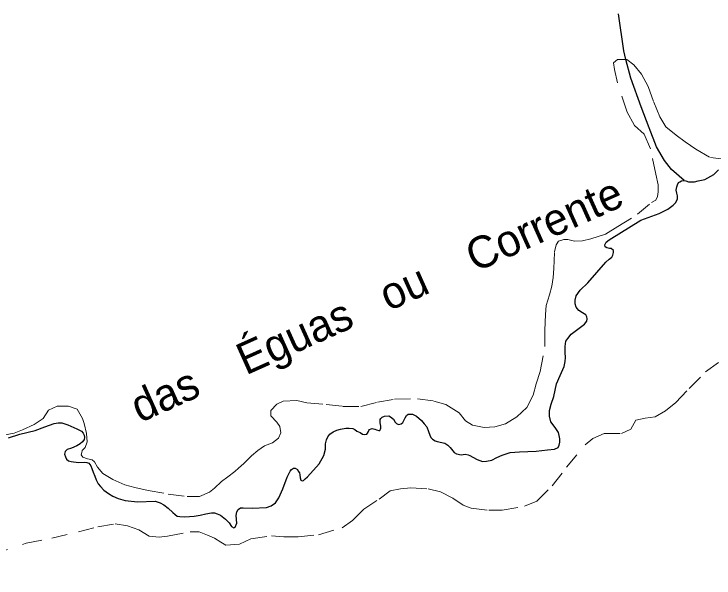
# Model space of a CAD drawing. Extents: x 391.8 to 446, y 8452 to 8507.5.
# Drawn here: x 426.92 to 431.31, y 8502.725 to 8506.265 of the extents above; entities that cross this region are included whole.
import ezdxf
from ezdxf.enums import TextEntityAlignment as Align

# ---------------------------------------------------------------- set-up
doc = ezdxf.new("R2010")
doc.units = 0
doc.header["$LTSCALE"] = 0.064
doc.linetypes.add('SHORT_DASHED', pattern=[2.7, 1.5, -1.2])
doc.layers.add('21', color=7, linetype='SHORT_DASHED', lineweight=13)
doc.layers.add('7', color=7, linetype='Continuous', lineweight=25)
doc.layers.add('61', color=7, linetype='Continuous')

msp = doc.modelspace()

# ---------------------------------------------------------------- linework, layer by layer
at = {"layer": '21'}
for points in [[(430.812, 8505.5655), (430.764, 8505.654), (430.7045, 8505.8321), (430.6861, 8505.9169), (430.6787, 8505.9575), (430.7045, 8505.9796), (430.758, 8505.9796)], [(430.758, 8505.9796), (430.7636, 8505.9796), (430.8079, 8505.9464), (430.8559, 8505.8874), (430.8965, 8505.81), (430.9334, 8505.7104), (430.9704, 8505.6183), (431.0073, 8505.5556), (431.0737, 8505.504), (431.1291, 8505.4634), (431.1956, 8505.4155), (431.2879, 8505.3638), (431.3728, 8505.3528)], [(430.956, 8505.1194), (430.9597, 8505.1489), (430.9597, 8505.1931), (430.9449, 8505.2595), (430.9117, 8505.418), (430.8711, 8505.5102), (430.812, 8505.5655)], [(426.8442, 8503.6189), (426.9217, 8503.6337), (426.9734, 8503.6558), (427.0472, 8503.689), (427.1026, 8503.7259), (427.1359, 8503.7775), (427.1912, 8503.8033), (427.2614, 8503.8033), (427.3168, 8503.7849), (427.35, 8503.7259), (427.3592, 8503.6942), (427.374, 8503.6315), (427.3777, 8503.5799), (427.3666, 8503.543), (427.3481, 8503.5246), (427.3445, 8503.5135), (427.3408, 8503.4988), (427.3518, 8503.484), (427.3814, 8503.473), (427.4109, 8503.4656), (427.4257, 8503.4545), (427.4441, 8503.4213), (427.4774, 8503.3808), (427.5401, 8503.3439), (427.614, 8503.3107), (427.6767, 8503.2923), (427.7616, 8503.2739), (427.8872, 8503.2517), (428.0053, 8503.237), (428.0828, 8503.237), (428.1456, 8503.2628), (428.1766, 8503.2896), (428.2209, 8503.3301), (428.2615, 8503.3596), (428.3058, 8503.3928), (428.328, 8503.4149), (428.3612, 8503.4444), (428.4092, 8503.4923), (428.4498, 8503.5255), (428.4904, 8503.555), (428.5421, 8503.5735), (428.579, 8503.603), (428.5938, 8503.6361), (428.5864, 8503.6767), (428.568, 8503.7025), (428.531, 8503.7431), (428.531, 8503.7763), (428.568, 8503.8168), (428.6086, 8503.8352), (428.6935, 8503.8389), (428.7562, 8503.8242), (428.8781, 8503.8131), (428.9815, 8503.8021), (429.0959, 8503.8021), (429.1993, 8503.8279), (429.3063, 8503.8463), (429.4503, 8503.85), (429.5537, 8503.8352), (429.6275, 8503.8131), (429.7125, 8503.7615), (429.7513, 8503.7104), (429.7956, 8503.6846), (429.8695, 8503.6698), (429.9359, 8503.6735), (430.0024, 8503.6919), (430.0725, 8503.7362), (430.1353, 8503.7952), (430.1759, 8503.8726), (430.1944, 8503.9427), (430.2202, 8504.0201), (430.2498, 8504.1786), (430.2493, 8504.2799), (430.253, 8504.3795), (430.2567, 8504.4348), (430.2788, 8504.5011), (430.2936, 8504.5564), (430.301, 8504.6117), (430.3047, 8504.667), (430.309, 8504.7716), (430.32, 8504.8158), (430.3348, 8504.838), (430.368, 8504.849), (430.3939, 8504.849), (430.4345, 8504.838), (430.4862, 8504.8416), (430.5379, 8504.8527), (430.6302, 8504.8822), (430.7077, 8504.9301), (430.8295, 8505.0076), (430.9181, 8505.0813), (430.9449, 8505.0972), (430.956, 8505.1194)], [(427.5547, 8503.0651), (427.6318, 8503.0523), (427.7025, 8503.0266), (427.7668, 8502.9881), (427.8311, 8502.9817), (427.8825, 8502.9881), (428.0239, 8503.0138), (428.0818, 8503.0138), (428.1332, 8502.9945), (428.1782, 8502.9753), (428.2168, 8502.9496), (428.2489, 8502.9303), (428.3351, 8502.9381), (428.4058, 8502.9702), (428.5343, 8502.9894), (428.6115, 8502.983), (428.7015, 8502.983), (428.83, 8502.9958), (428.9779, 8503.0408), (429.0422, 8503.0857), (429.1129, 8503.1563), (429.2093, 8503.2205), (429.28, 8503.2719), (429.3443, 8503.2847), (429.4086, 8503.2912), (429.5179, 8503.2847), (429.595, 8503.2655), (429.6722, 8503.227), (429.7364, 8503.182), (429.7879, 8503.1628), (429.8972, 8503.1499), (429.9807, 8503.1499), (430.1221, 8503.1756), (430.1993, 8503.2077), (430.2957, 8503.304), (430.3857, 8503.4196), (430.5014, 8503.5608), (430.5499, 8503.6007), (430.6206, 8503.6328), (430.7299, 8503.6328), (430.7877, 8503.6585), (430.8199, 8503.7163), (430.8777, 8503.7291), (430.942, 8503.7355), (431.0063, 8503.774), (431.0706, 8503.8254), (431.1541, 8503.9153), (431.257, 8504.018), (431.3811, 8504.1102)], [(426.4811, 8502.7249), (426.7833, 8502.8725), (426.9954, 8502.9432), (427.1561, 8502.9753), (427.3233, 8503.0138), (427.4454, 8503.0459), (427.5547, 8503.0651)]]:
    msp.add_lwpolyline(points, dxfattribs=at)
at = {"layer": '7'}
for points in [[(430.758, 8505.9796), (430.7446, 8506.0333), (430.7115, 8506.2647)], [(431.1232, 8505.219), (431.0426, 8505.2893), (430.9995, 8505.3455), (430.9499, 8505.4315), (430.9035, 8505.5505), (430.8538, 8505.6828), (430.7876, 8505.8613), (430.758, 8505.9796)], [(431.1232, 8505.219), (431.1332, 8505.217), (431.1499, 8505.2123), (431.1879, 8505.2123), (431.2117, 8505.217), (431.2521, 8505.2265), (431.3092, 8505.2574), (431.3384, 8505.2875)], [(430.5061, 8504.377), (430.4848, 8504.3897), (430.4613, 8504.4047), (430.4464, 8504.4238), (430.44, 8504.4451), (430.44, 8504.4686), (430.4464, 8504.4963), (430.4699, 8504.5304), (430.5189, 8504.5772), (430.632, 8504.7072), (430.6534, 8504.7252), (430.6683, 8504.738), (430.6747, 8504.7508), (430.679, 8504.7678), (430.679, 8504.7806), (430.6641, 8504.7934), (430.6555, 8504.7934), (430.6385, 8504.7977), (430.6278, 8504.804), (430.6257, 8504.8168), (430.6342, 8504.8317), (430.6534, 8504.8467), (430.8518, 8504.9702), (430.9668, 8505.0128), (431.0215, 8505.0389), (431.0548, 8505.065), (431.069, 8505.0793), (431.0809, 8505.103), (431.0809, 8505.1244), (431.0762, 8505.141), (431.0738, 8505.16), (431.0762, 8505.179), (431.0809, 8505.1933), (431.088, 8505.2075), (431.0952, 8505.2123), (431.1071, 8505.217), (431.1213, 8505.2194), (431.1232, 8505.219)], [(430.3931, 8504.2289), (430.4144, 8504.2544), (430.4976, 8504.3183), (430.5125, 8504.3365), (430.5147, 8504.3514), (430.5125, 8504.3642), (430.5061, 8504.377)], [(428.9448, 8503.6529), (428.9683, 8503.6593), (429.0003, 8503.6657), (429.0216, 8503.6657), (429.0451, 8503.6635), (429.0579, 8503.6571), (429.0707, 8503.6465), (429.0899, 8503.638), (429.1048, 8503.6273), (429.1176, 8503.6252), (429.1326, 8503.6273), (429.1368, 8503.6337), (429.1432, 8503.6443), (429.1454, 8503.6507), (429.1496, 8503.6571), (429.1603, 8503.6614), (429.1667, 8503.6635), (429.1838, 8503.6593), (429.1923, 8503.655), (429.2072, 8503.6507), (429.2136, 8503.6507), (429.2179, 8503.6593), (429.22, 8503.6657), (429.22, 8503.6784), (429.2158, 8503.6997), (429.2158, 8503.7189), (429.22, 8503.7253), (429.2286, 8503.7338), (429.2435, 8503.7402), (429.2712, 8503.7423), (429.2819, 8503.736), (429.2989, 8503.721), (429.3096, 8503.704), (429.3181, 8503.6955), (429.3309, 8503.6891), (429.348, 8503.6933), (429.3587, 8503.7019), (429.3672, 8503.7168), (429.3736, 8503.7296), (429.3821, 8503.7445), (429.3928, 8503.753), (429.4184, 8503.753), (429.444, 8503.7402), (429.476, 8503.7125), (429.4931, 8503.6933), (429.508, 8503.6742), (429.5187, 8503.6443), (429.5272, 8503.6209), (429.5336, 8503.606), (429.5443, 8503.5953), (429.5613, 8503.5868), (429.5741, 8503.5826), (429.6211, 8503.5719), (429.6403, 8503.5591), (429.6552, 8503.5442), (429.6723, 8503.5229), (429.6808, 8503.5123), (429.6957, 8503.5037), (429.7235, 8503.4973), (429.75, 8503.5015), (429.7692, 8503.4972), (429.7777, 8503.493), (429.7969, 8503.4823), (429.8247, 8503.4695), (429.8588, 8503.4568), (429.8823, 8503.4589), (429.9164, 8503.4653), (429.9484, 8503.4802), (429.9825, 8503.4951), (430.0316, 8503.5122), (430.0892, 8503.5164), (430.1937, 8503.5207), (430.2662, 8503.5292), (430.3089, 8503.5335), (430.3324, 8503.5441), (430.3388, 8503.559), (430.343, 8503.5782), (430.343, 8503.5974), (430.3388, 8503.6187), (430.3345, 8503.6378), (430.3132, 8503.6698), (430.2876, 8503.706), (430.279, 8503.7401), (430.279, 8503.7763), (430.2897, 8503.8168), (430.3046, 8503.8637), (430.3227, 8503.9434), (430.3462, 8503.9967), (430.3696, 8504.052), (430.376, 8504.084), (430.3782, 8504.1096), (430.376, 8504.1394), (430.376, 8504.1777), (430.3803, 8504.2118), (430.3931, 8504.2289)], [(426.8853, 8503.6037), (426.9557, 8503.6271), (427.0517, 8503.6506), (427.1135, 8503.674), (427.1711, 8503.6953), (427.1967, 8503.6996), (427.2202, 8503.6996), (427.2565, 8503.6868), (427.3141, 8503.6612), (427.3439, 8503.6463), (427.3546, 8503.6335), (427.3589, 8503.6208), (427.361, 8503.6058), (427.3589, 8503.5952), (427.3503, 8503.5803), (427.3354, 8503.5675), (427.3141, 8503.5547), (427.2799, 8503.5398), (427.2543, 8503.5313), (427.2415, 8503.5185), (427.2373, 8503.5015), (427.2437, 8503.4844), (427.2501, 8503.4716), (427.2607, 8503.461), (427.2778, 8503.4567), (427.3247, 8503.4503), (427.3597, 8503.4518), (427.3768, 8503.4497), (427.3896, 8503.4454), (427.4024, 8503.4284), (427.4088, 8503.4113), (427.4173, 8503.39), (427.4259, 8503.3645), (427.4344, 8503.341), (427.4472, 8503.3155), (427.4621, 8503.2984), (427.4835, 8503.2771), (427.5133, 8503.2558), (427.5389, 8503.2388), (427.5731, 8503.2238), (427.6179, 8503.2111), (427.6946, 8503.2025), (427.8056, 8503.2068), (427.8362, 8503.1971), (427.8597, 8503.1843), (427.8874, 8503.163), (427.9151, 8503.1353), (427.9301, 8503.1225), (427.9429, 8503.114), (427.9599, 8503.1119), (427.9919, 8503.1098), (428.0495, 8503.114), (428.0879, 8503.1183), (428.123, 8503.1272), (428.1593, 8503.1336), (428.1768, 8503.1339), (428.1946, 8503.1268), (428.2159, 8503.1183), (428.2458, 8503.0949), (428.2693, 8503.0714), (428.2836, 8503.0483), (428.2985, 8503.0398), (428.3077, 8503.0437), (428.3171, 8503.0689), (428.3141, 8503.1162), (428.3183, 8503.1405), (428.3251, 8503.1551), (428.3411, 8503.1644), (428.3567, 8503.1652), (428.4143, 8503.163), (428.5039, 8503.1673), (428.5324, 8503.1789), (428.5601, 8503.196), (428.5814, 8503.2279), (428.6049, 8503.2854), (428.6326, 8503.3579), (428.6518, 8503.3962), (428.6604, 8503.4069), (428.6732, 8503.4133), (428.6838, 8503.4133), (428.6988, 8503.4069), (428.703, 8503.3962), (428.7094, 8503.3856), (428.7116, 8503.3728), (428.7137, 8503.3536), (428.718, 8503.3387), (428.7265, 8503.3344), (428.735, 8503.3366), (428.7457, 8503.3472), (428.7606, 8503.36), (428.8332, 8503.441), (428.8638, 8503.4931), (428.8744, 8503.5336)], [(428.8744, 8503.5336), (428.8744, 8503.5676), (428.8787, 8503.5911), (428.8872, 8503.6103), (428.9, 8503.6273), (428.9214, 8503.6422), (428.9448, 8503.6529)]]:
    msp.add_lwpolyline(points, dxfattribs=at)

# ---------------------------------------------------------------- texts
at = {"layer": '61'}
msp.add_text('Rio                        das    Éguas   ou    Corrente', height=0.2, rotation=24.199, dxfattribs=at).set_placement((428.2385, 8503.9345), align=Align.CENTER)

doc.saveas('drawing.dxf')
